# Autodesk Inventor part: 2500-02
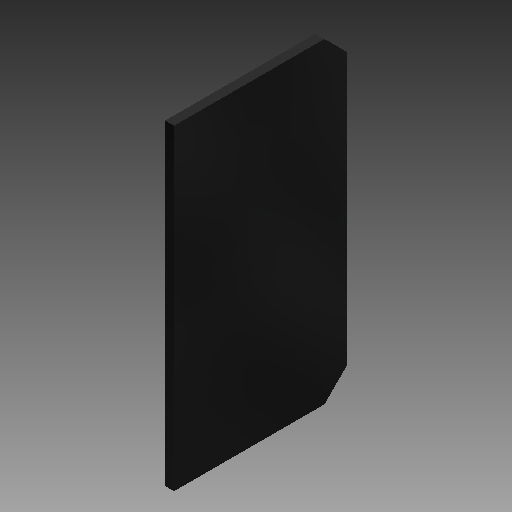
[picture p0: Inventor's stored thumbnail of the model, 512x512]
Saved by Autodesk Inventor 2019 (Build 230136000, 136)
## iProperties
Company: Autodesk Inc.
Created: 2006-01
Part Number: 2500-02
Document SubType Name: Modeling
Designer: Autodesk Inc.
Density: 1.06 g/cm^3
Mass: 5.70121 g
Surface Area: 58.0278 cm^2
Volume: 5.3785 cm^3
Material: ABS Plastic
Appearance: Smooth - Black
Description: REAR CARTRIDGE PANEL
Author: Inventor
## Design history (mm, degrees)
sketch "Sketch1"
  geometry: L1 (-35.25, 19.25)-(35.25, 19.25); L2 (35.25, 19.25)-(35.25, -19.25); L3 (35.25, -19.25)-(-35.25, -19.25); L4 (-35.25, -19.25)-(-35.25, 19.25); L5 (0, 26.95)-(0, -26.95) reference; L6 (-49.35, 0)-(49.35, 0) reference
  constraints: 8 end point, 2 parallel, 1 horizontal, 1 perpendicular, 2 other
  dimensions: "d0" = 70.5 distance of L1.start L1.end; "d1" = 38.5 distance of L1.end L2.end
extrude "Extrusion1" new body sketch "Sketch1" distance "d2" = 2; taper "d3" = 0 deg
chamfer "Chamfer1" distance "d4" = 5; stored, may be unused: second distance "d5" = 2, angle "d6" = 45 deg
body "Solid1"
